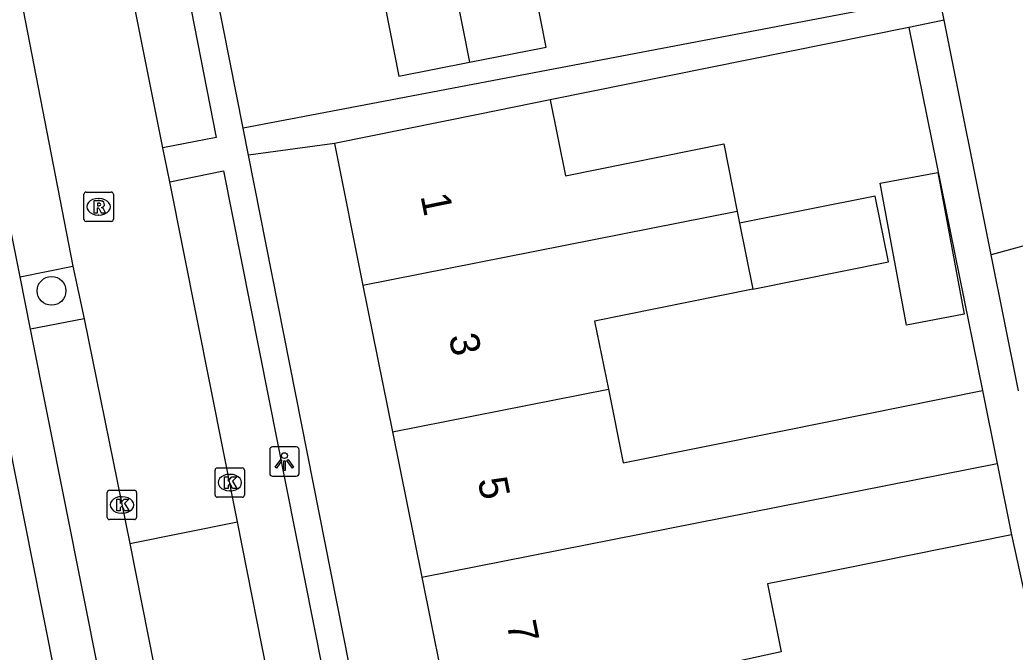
# Model space of a CAD drawing. Extents: x 162250 to 162654, y 380744 to 381605.
# Drawn here: x 162499.28 to 162533.18, y 381100.24 to 381121.76 of the extents above; entities that cross this region are included whole.
import ezdxf

# ---------------------------------------------------------------- set-up
doc = ezdxf.new("R2010")
doc.units = 0
for name, color, linetype in [('IMGEO_Boom', 7, 'Continuous'), ('IMGEO_Kolk', 7, 'Continuous'), ('IMGEO_Lichtpunt', 7, 'Continuous'), ('IMGEO_Pand', 7, 'Continuous'), ('IMGEO_Pand_nummerreeks', 7, 'Continuous'), ('IMGEO_Pand_vergunning_verleend', 7, 'Continuous'), ('IMGEO_Parkeervlak_open', 7, 'Continuous'), ('IMGEO_Rioolput', 7, 'Continuous'), ('IMGEO_Voetpad_open', 7, 'Continuous'), ('IMGEO_Woonerf_open', 7, 'Continuous')]:
    doc.layers.add(name, color=color, linetype=linetype)

msp = doc.modelspace()

# ---------------------------------------------------------------- linework, layer by layer
at = {"layer": 'IMGEO_Boom'}
msp.add_circle((162500.356, 381112.535), 0.489, dxfattribs=at)
at = {"layer": 'IMGEO_Kolk'}
for p, q in [((162505.927, 381105.584), (162505.927, 381106.436)), ((162506.002, 381106.51), (162506.854, 381106.51)), ((162506.928, 381106.436), (162506.928, 381105.584)), ((162506.415, 381106.29), (162506.44, 381106.29)), ((162502.328, 381105.749), (162503.18, 381105.749)), ((162506.438, 381105.73), (162506.413, 381105.73)), ((162502.253, 381104.823), (162502.253, 381105.675)), ((162502.741, 381105.529), (162502.766, 381105.529)), ((162503.254, 381105.675), (162503.254, 381104.823)), ((162506.854, 381105.51), (162506.002, 381105.51)), ((162503.18, 381104.749), (162502.328, 381104.749)), ((162502.764, 381104.969), (162502.739, 381104.969))]:
    msp.add_line(p, q, dxfattribs=at)
for points in [[(162505.927, 381105.584), (162505.927, 381106.436)], [(162506.002, 381106.51), (162506.854, 381106.51)], [(162506.928, 381106.436), (162506.928, 381105.584)], [(162506.248, 381106.21), (162506.371, 381106.21), (162506.371, 381106.059), (162506.501, 381106.21), (162506.665, 381106.21), (162506.519, 381106.059), (162506.672, 381105.81), (162506.52, 381105.81), (162506.435, 381105.974), (162506.371, 381105.907), (162506.371, 381105.81), (162506.248, 381105.81), (162506.248, 381106.21)], [(162502.328, 381105.749), (162503.18, 381105.749)], [(162502.253, 381104.823), (162502.253, 381105.675)], [(162502.574, 381105.449), (162502.697, 381105.449), (162502.697, 381105.298), (162502.827, 381105.449), (162502.991, 381105.449), (162502.845, 381105.298), (162502.998, 381105.049), (162502.846, 381105.049), (162502.761, 381105.213), (162502.697, 381105.146), (162502.697, 381105.049), (162502.574, 381105.049), (162502.574, 381105.449)], [(162503.254, 381105.675), (162503.254, 381104.823)], [(162506.854, 381105.51), (162506.002, 381105.51)], [(162503.18, 381104.749), (162502.328, 381104.749)]]:
    msp.add_lwpolyline(points, dxfattribs=at)
for centre, start, end in [((162506.004, 381106.434), 91.552, 178.448), ((162506.004, 381106.434), 91.552, 178.448), ((162506.852, 381106.434), 1.552, 88.448), ((162506.852, 381106.434), 1.552, 88.448), ((162502.33, 381105.673), 91.552, 178.448), ((162502.33, 381105.673), 91.552, 178.448), ((162503.178, 381105.673), 1.552, 88.448), ((162503.178, 381105.673), 1.552, 88.448), ((162506.004, 381105.586), 181.552, 268.448), ((162506.004, 381105.586), 181.552, 268.448), ((162506.852, 381105.586), 271.552, 358.448), ((162506.852, 381105.586), 271.552, 358.448), ((162502.33, 381104.825), 181.552, 268.448), ((162502.33, 381104.825), 181.552, 268.448), ((162503.178, 381104.825), 271.552, 358.448), ((162503.178, 381104.825), 271.552, 358.448)]:
    msp.add_arc(centre, 0.0765, start, end, dxfattribs=at)
for centre, major_axis, ratio, start_param, end_param in [((162506.414, 381106.01), (-0.387, 0.002), 0.722429, 4.712389, 7.853982), ((162506.439, 381106.01), (-0.39, 0.002), 0.717154, 1.570796, 4.712389), ((162502.74, 381105.249), (-0.387, 0.002), 0.722429, 4.712389, 7.853982), ((162502.765, 381105.249), (-0.39, 0.002), 0.717154, 1.570796, 4.712389)]:
    msp.add_ellipse(centre, major_axis=major_axis, ratio=ratio, start_param=start_param, end_param=end_param, dxfattribs=at)
at = {"layer": 'IMGEO_Lichtpunt'}
for p, q in [((162507.789, 381107.129), (162507.789, 381106.322)), ((162507.789, 381107.129), (162507.789, 381106.322)), ((162508.691, 381107.224), (162507.883, 381107.224)), ((162508.691, 381107.224), (162507.883, 381107.224)), ((162508.785, 381106.322), (162508.785, 381107.129)), ((162508.785, 381106.322), (162508.785, 381107.129)), ((162507.883, 381106.228), (162508.691, 381106.228)), ((162507.883, 381106.228), (162508.691, 381106.228))]:
    msp.add_line(p, q, dxfattribs=at)
for points in [[(162508.163, 381106.793), (162508.202, 381106.765), (162508.014, 381106.503), (162507.976, 381106.53), (162508.163, 381106.793)], [(162508.265, 381106.745), (162508.312, 381106.745), (162508.312, 381106.423), (162508.265, 381106.423), (162508.265, 381106.745)], [(162508.375, 381106.765), (162508.413, 381106.792), (162508.6, 381106.53), (162508.561, 381106.502), (162508.375, 381106.765)]]:
    msp.add_lwpolyline(points, dxfattribs=at)
msp.add_circle((162508.288, 381106.927), 0.0994, dxfattribs=at)
for centre, start, end in [((162507.883, 381107.129), 90, 180), ((162507.883, 381107.129), 90, 180), ((162508.691, 381107.129), 0, 90), ((162508.691, 381107.129), 0, 90), ((162507.883, 381106.322), 180, 270), ((162507.883, 381106.322), 180, 270), ((162508.691, 381106.322), 270, 0), ((162508.691, 381106.322), 270, 360)]:
    msp.add_arc(centre, 0.0946, start, end, dxfattribs=at)
at = {"layer": 'IMGEO_Pand'}
for points in [[(162512.068, 381133.049), (162507.119, 381132.075), (162507.502, 381130.131), (162504.869, 381129.623), (162505.385, 381126.943), (162508.029, 381127.452), (162508.558, 381124.767), (162511.118, 381125.271), (162512.186, 381119.842), (162514.589, 381120.315)], [(162512.068, 381133.049), (162514.589, 381120.315)], [(162514.589, 381120.315), (162517.093, 381120.807), (162517.199, 381120.828), (162516.135, 381126.235), (162518.344, 381126.67)], [(162538.456, 381119.316), (162539.296, 381116.244), (162536.185, 381115.393), (162536.335, 381114.848), (162532.362, 381113.762)], [(162517.345, 381119.039), (162514.89, 381118.544), (162509.988, 381117.556)], [(162517.345, 381119.039), (162517.866, 381116.451), (162523.25, 381117.536), (162523.713, 381115.239)], [(162509.988, 381117.556), (162510.963, 381112.717)], [(162524.246, 381112.595), (162528.863, 381113.526), (162528.414, 381115.754), (162523.793, 381114.84)], [(162523.713, 381115.239), (162510.963, 381112.717)], [(162523.713, 381115.239), (162523.793, 381114.84)], [(162523.793, 381114.84), (162524.246, 381112.595)], [(162533.293, 381109.132), (162532.362, 381113.762)], [(162510.963, 381112.717), (162511.966, 381107.741)], [(162524.246, 381112.595), (162518.855, 381111.508), (162519.323, 381109.185)], [(162511.966, 381107.741), (162519.323, 381109.185)], [(162519.323, 381109.185), (162519.827, 381106.682), (162525.256, 381107.777), (162532.063, 381109.148)], [(162532.063, 381109.148), (162532.568, 381106.657)], [(162511.966, 381107.741), (162512.964, 381102.792)], [(162512.964, 381102.792), (162532.568, 381106.657)], [(162532.568, 381106.657), (162533.059, 381104.234)], [(162533.059, 381104.234), (162526.247, 381102.862), (162524.738, 381102.558), (162525.203, 381100.253), (162521.604, 381099.461)], [(162512.964, 381102.792), (162513.93, 381097.999)]]:
    msp.add_lwpolyline(points, dxfattribs=at)
at = {"layer": 'IMGEO_Pand_vergunning_verleend'}
msp.add_lwpolyline([(162528.579, 381116.202), (162530.543, 381116.566), (162531.438, 381111.737), (162529.474, 381111.373), (162528.579, 381116.202)], dxfattribs=at)
at = {"layer": 'IMGEO_Parkeervlak_open'}
for points in [[(162504.15, 381117.408), (162501.543, 381130.412)], [(162498.718, 381125.553), (162501.08, 381113.372)], [(162506.695, 381104.669), (162504.39, 381116.243)], [(162499.29, 381113.013), (162501.08, 381113.372)], [(162501.467, 381111.579), (162499.637, 381111.231)], [(162501.467, 381111.579), (162503.021, 381103.934)], [(162507.858, 381098.746), (162506.695, 381104.669)], [(162503.021, 381103.934), (162503.85, 381099.749)]]:
    msp.add_lwpolyline(points, dxfattribs=at)
at = {"layer": 'IMGEO_Rioolput'}
for p, q in [((162501.535, 381115.897), (162502.387, 381115.897)), ((162501.46, 381114.971), (162501.46, 381115.823)), ((162501.948, 381115.677), (162501.973, 381115.677)), ((162502.461, 381115.823), (162502.461, 381114.971)), ((162502.387, 381114.897), (162501.535, 381114.897)), ((162501.971, 381115.117), (162501.946, 381115.117))]:
    msp.add_line(p, q, dxfattribs=at)
for points in [[(162501.535, 381115.897), (162502.387, 381115.897)], [(162501.46, 381114.971), (162501.46, 381115.823)], [(162502.049, 381115.595), (162501.797, 381115.597), (162501.797, 381115.197)], [(162501.975, 381115.516), (162501.921, 381115.516), (162501.921, 381115.435)], [(162502.461, 381115.823), (162502.461, 381114.971)], [(162501.797, 381115.197), (162501.921, 381115.197), (162501.921, 381115.359), (162501.932, 381115.359)], [(162501.921, 381115.435), (162501.973, 381115.435)], [(162501.979, 381115.33), (162502.05, 381115.197), (162502.19, 381115.197), (162502.125, 381115.323)], [(162502.387, 381114.897), (162501.535, 381114.897)]]:
    msp.add_lwpolyline(points, dxfattribs=at)
for centre, radius, start, end in [((162501.537, 381115.821), 0.0765, 91.552, 178.448), ((162501.537, 381115.821), 0.0765, 91.552, 178.448), ((162502.385, 381115.821), 0.0765, 1.552, 88.448), ((162502.385, 381115.821), 0.0765, 1.552, 88.448), ((162501.981, 381115.42), 0.0964, 77.0061, 93.1865), ((162501.995, 381115.477), 0.0378, 276.6634, 79.6772), ((162502.048, 381115.485), 0.109, 350.3612, 89.416), ((162501.931, 381115.306), 0.0533, 26.0293, 88.6989), ((162501.957, 381115.624), 0.19, 274.7715, 282.9687), ((162502.046, 381115.485), 0.112, 277.5842, 350.9817), ((162502.03, 381115.27), 0.108, 29.5134, 73.7905), ((162501.537, 381114.973), 0.0765, 181.552, 268.448), ((162501.537, 381114.973), 0.0765, 181.552, 268.448), ((162502.385, 381114.973), 0.0765, 271.552, 358.448), ((162502.385, 381114.973), 0.0765, 271.552, 358.448)]:
    msp.add_arc(centre, radius, start, end, dxfattribs=at)
for centre, major_axis, ratio, start_param, end_param in [((162501.947, 381115.397), (-0.387, 0.002), 0.722429, 4.712389, 7.853982), ((162501.972, 381115.397), (-0.39, 0.002), 0.717154, 1.570796, 4.712389)]:
    msp.add_ellipse(centre, major_axis=major_axis, ratio=ratio, start_param=start_param, end_param=end_param, dxfattribs=at)
at = {"layer": 'IMGEO_Voetpad_open'}
for points in [[(162506.878, 381118.071), (162503.939, 381132.922)], [(162501.543, 381130.412), (162503.419, 381130.742), (162505.965, 381117.753), (162504.15, 381117.408)], [(162499.29, 381113.013), (162496.851, 381125.168)], [(162530.755, 381121.745), (162530.585, 381122.589), (162506.878, 381118.071)], [(162530.755, 381121.745), (162529.559, 381121.504)], [(162532.362, 381113.762), (162530.755, 381121.745)], [(162529.559, 381121.504), (162517.345, 381119.039)], [(162529.559, 381121.504), (162532.063, 381109.148)], [(162507.059, 381117.156), (162506.878, 381118.071)], [(162509.988, 381117.556), (162507.059, 381117.156)], [(162504.39, 381116.243), (162504.15, 381117.408)], [(162517.527, 381064.258), (162507.059, 381117.156)], [(162504.39, 381116.243), (162506.211, 381116.622), (162516.305, 381065.809)], [(162497.47, 381114.509), (162500, 381101.818), (162507.87, 381062.342)], [(162499.637, 381111.231), (162499.29, 381113.013)], [(162501.998, 381099.383), (162499.637, 381111.231)], [(162533.059, 381104.234), (162534.676, 381096.835)]]:
    msp.add_lwpolyline(points, dxfattribs=at)
at = {"layer": 'IMGEO_Woonerf_open'}
for points in [[(162501.08, 381113.372), (162501.467, 381111.579)], [(162503.021, 381103.934), (162506.695, 381104.669)]]:
    msp.add_lwpolyline(points, dxfattribs=at)

# ---------------------------------------------------------------- texts
at = {"layer": 'IMGEO_Pand_nummerreeks'}
for s, rotation, p in [('1', 281.3958, (162512.919, 381115.767)), ('3', 281.3959, (162513.882, 381110.99)), ('5', 281.3958, (162514.867, 381106.101)), ('7', 281.3958, (162515.853, 381101.212))]:
    msp.add_text(s, height=1, rotation=rotation, dxfattribs=at).set_placement(p)

doc.saveas('drawing.dxf')
